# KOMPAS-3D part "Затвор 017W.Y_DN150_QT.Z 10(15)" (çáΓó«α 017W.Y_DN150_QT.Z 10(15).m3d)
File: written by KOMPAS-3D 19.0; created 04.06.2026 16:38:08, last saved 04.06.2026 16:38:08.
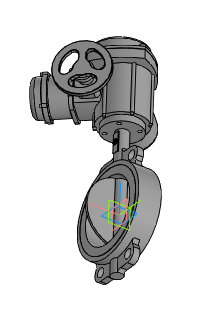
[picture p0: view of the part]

Document properties: Автор: Энергия; Полное имя файла: ..\..\..\3d для проектировщиков\017W разные\x.x Тип 017W.Y(S) Затвор дисковый поворотный межфланцевый\Затвор 017W.Y(S)_DN32-DN450_QT.Z\Затвор 017W.Y_DN150_PN10_QT.Z 10.a3d

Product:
- Part/product: Затвор 017W.Y_DN150_QT.Z 10(15)
    Масса: 37.8655

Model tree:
1. Операция без истории:1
